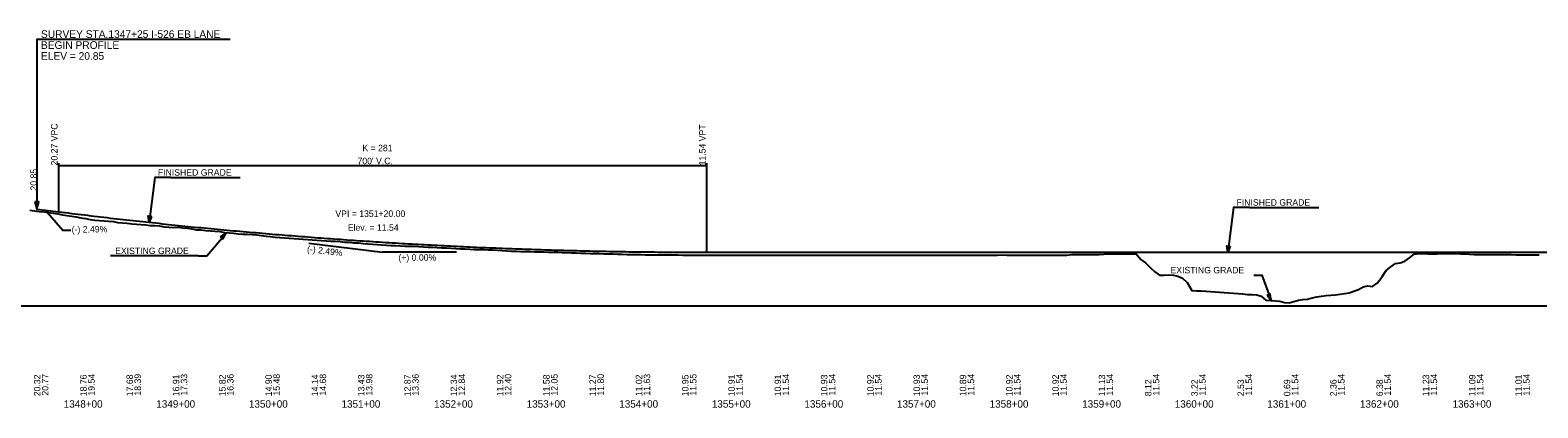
# Model space of a CAD drawing. Extents: x 2360994 to 2383826, y 330623 to 403123.
# Drawn here: x 2370065 to 2371693, y 356763 to 357170 of the extents above; entities that cross this region are included whole.
import ezdxf

# ---------------------------------------------------------------- set-up
doc = ezdxf.new("R2010")
doc.units = 0
for name, color, linetype in [('RD_DDB_GradeTX', 7, 'Continuous'), ('RD_DDB_Profile_EX', 7, 'Continuous'), ('RD_DDB_Profile_Lbl', 7, 'Continuous'), ('RD_DDB_Profile_PR', 7, 'Continuous'), ('RD_DDB_StaTX', 7, 'Continuous'), ('RD_DDB_StripGrade', 7, 'Continuous'), ('RD_DDB_VCLbl', 7, 'Continuous'), ('RD_GPK_Profile_Cell', 7, 'Continuous'), ('RD_TX_Profile', 7, 'Continuous')]:
    doc.layers.add(name, color=color, linetype=linetype)

msp = doc.modelspace()

# ---------------------------------------------------------------- linework, layer by layer
at = {"layer": 'RD_DDB_GradeTX'}
for p in [(2370366.2, 356940.5), (2370525.6, 356930.6)]:
    msp.add_line(p, (2370445.6, 356930.6), dxfattribs=at)
at = {"layer": 'RD_DDB_Profile_EX'}
for points in [[(2370064.8, 356975.9), (2370069.8, 356975.2), (2370074.8, 356974.6), (2370079.8, 356974), (2370084.8, 356973.5), (2370089.8, 356972.8), (2370094.8, 356972.1), (2370099.8, 356971), (2370104.8, 356970.1), (2370109.8, 356969.4), (2370114.8, 356968.6), (2370119.8, 356967.8), (2370124.8, 356966.8), (2370129.8, 356965.9), (2370134.8, 356965.3), (2370139.8, 356964.9), (2370144.8, 356964.4), (2370149.8, 356964), (2370154.8, 356963.6), (2370159.8, 356962.8), (2370164.8, 356962.2), (2370169.8, 356961.8), (2370174.8, 356961.4), (2370179.8, 356960.9), (2370184.8, 356960.4), (2370189.8, 356960), (2370194.8, 356959.5), (2370199.8, 356959.4), (2370204.8, 356959), (2370209.8, 356957.9), (2370214.8, 356957.5), (2370219.8, 356957.1), (2370224.8, 356957.5), (2370229.8, 356957), (2370234.8, 356956.5), (2370239.8, 356956), (2370244.8, 356954.7), (2370249.8, 356954.7), (2370254.8, 356954.2), (2370259.8, 356953.8), (2370264.8, 356953.4), (2370269.8, 356953), (2370274.8, 356952), (2370279.8, 356951.6), (2370284.8, 356951.1), (2370289.8, 356950.6), (2370294.8, 356950.2), (2370299.8, 356950), (2370304.8, 356949.6), (2370309.8, 356949.2), (2370314.8, 356948.7), (2370319.8, 356947.9), (2370324.8, 356947.5), (2370329.8, 356947), (2370334.8, 356946.6), (2370339.8, 356946.2), (2370344.8, 356945.7), (2370349.8, 356945.3), (2370354.8, 356944.9), (2370359.8, 356944.6), (2370364.8, 356944.2), (2370369.8, 356943.9), (2370374.8, 356943.6), (2370379.8, 356943.3), (2370384.8, 356943), (2370389.8, 356942.7), (2370394.8, 356942.4), (2370399.8, 356942), (2370404.8, 356941.6), (2370409.8, 356941.3), (2370414.8, 356940.9), (2370419.8, 356940.6), (2370424.8, 356940.1), (2370429.8, 356939.7), (2370434.8, 356939.4), (2370439.8, 356939.1), (2370444.8, 356938.7), (2370449.8, 356938.3), (2370454.8, 356938), (2370459.8, 356937.7), (2370464.8, 356937.4), (2370469.8, 356937.2), (2370474.8, 356937.3), (2370479.8, 356937), (2370484.8, 356936.8), (2370489.8, 356936.5), (2370494.8, 356936), (2370499.8, 356935.9), (2370504.8, 356935.7), (2370509.8, 356935.4), (2370514.8, 356935.2), (2370519.8, 356935), (2370524.8, 356934.6), (2370529.8, 356934.4), (2370534.8, 356934.2), (2370539.8, 356933.9), (2370544.8, 356933.7), (2370549.8, 356933.5), (2370554.8, 356933.4), (2370559.8, 356933.2), (2370564.8, 356933.1)], [(2370564.8, 356933.1), (2370569.8, 356932.8), (2370574.8, 356932.5), (2370579.8, 356932.2), (2370584.8, 356931.9), (2370589.8, 356931.6), (2370594.8, 356931.4), (2370599.8, 356931.4), (2370604.8, 356931.3), (2370609.8, 356931.2), (2370614.8, 356931.1), (2370619.8, 356930.9), (2370624.8, 356930.8), (2370629.8, 356930.6), (2370634.8, 356930.5), (2370639.8, 356930.3), (2370644.8, 356930.2), (2370649.8, 356930), (2370654.8, 356929.9), (2370659.8, 356929.7), (2370664.8, 356929.6), (2370669.8, 356929.4), (2370674.8, 356929.3), (2370679.8, 356929.1), (2370684.8, 356929), (2370689.8, 356928.9), (2370694.8, 356928.7), (2370699.8, 356928.5), (2370704.8, 356928.4), (2370709.8, 356928.2), (2370714.8, 356928), (2370719.8, 356928), (2370724.8, 356928), (2370729.8, 356927.9), (2370734.8, 356927.9), (2370739.8, 356927.9), (2370744.8, 356927.9), (2370749.8, 356927.8), (2370754.8, 356927.8), (2370759.8, 356927.7), (2370764.8, 356927.7), (2370769.8, 356927.6), (2370774.8, 356927.6), (2370779.8, 356927.6), (2370784.8, 356927.6), (2370789.8, 356927.5), (2370794.8, 356927.5), (2370799.8, 356927.4), (2370804.8, 356927.5), (2370809.8, 356927.5), (2370814.8, 356927.5), (2370819.8, 356927.5), (2370824.8, 356927.4), (2370829.8, 356927.4), (2370834.8, 356927.4), (2370839.8, 356927.4), (2370844.8, 356927.3), (2370849.8, 356927.3), (2370854.8, 356927.4), (2370859.8, 356927.4), (2370864.8, 356927.4), (2370869.8, 356927.3), (2370874.8, 356927.4), (2370879.8, 356927.4), (2370884.8, 356927.4), (2370889.8, 356927.4), (2370894.8, 356927.4), (2370899.8, 356927.4), (2370904.8, 356927.4), (2370909.8, 356927.4), (2370914.8, 356927.4), (2370919.8, 356927.5), (2370924.8, 356927.5), (2370929.8, 356927.5), (2370934.8, 356927.6), (2370939.8, 356927.6), (2370944.8, 356927.6), (2370949.8, 356927.6), (2370954.8, 356927.5), (2370959.8, 356927.5), (2370964.8, 356927.5), (2370969.8, 356927.5), (2370974.8, 356927.5), (2370979.8, 356927.4), (2370984.8, 356927.4), (2370989.8, 356927.4), (2370994.8, 356927.3), (2370999.8, 356927.4), (2371004.8, 356927.4), (2371009.8, 356927.4), (2371014.8, 356927.4), (2371019.8, 356927.5), (2371024.8, 356927.5), (2371029.8, 356927.6), (2371034.8, 356927.6), (2371039.8, 356927.6), (2371044.8, 356927.5), (2371049.8, 356927.5), (2371054.8, 356927.5), (2371059.8, 356927.5), (2371064.8, 356927.5)], [(2371064.8, 356927.5), (2371069.8, 356927.4), (2371074.8, 356927.4), (2371079.8, 356927.3), (2371084.8, 356927.3), (2371089.8, 356927.3), (2371094.8, 356927.4), (2371099.8, 356927.4), (2371104.8, 356927.4), (2371109.8, 356927.4), (2371114.8, 356927.8), (2371119.8, 356927.5), (2371124.8, 356927.5), (2371129.8, 356927.5), (2371134.8, 356927.5), (2371139.8, 356927.5), (2371144.8, 356927.6), (2371149.8, 356927.6), (2371154.8, 356927.6), (2371159.8, 356927.6), (2371164.8, 356927.4), (2371169.8, 356927.4), (2371174.8, 356927.5), (2371179.8, 356927.5), (2371184.8, 356927.5), (2371189.8, 356928), (2371194.8, 356928.3), (2371199.8, 356928.3), (2371204.8, 356928.3), (2371209.8, 356928.3), (2371214.8, 356928.3), (2371219.8, 356928.2), (2371224.8, 356928.5), (2371229.8, 356928.9), (2371234.8, 356928.9), (2371239.8, 356928.9), (2371244.8, 356928.9), (2371249.8, 356928.9), (2371254.8, 356928.9), (2371259.8, 356928.9), (2371264.8, 356922.9), (2371269.8, 356919.3), (2371274.8, 356914.2), (2371279.8, 356909.5), (2371284.8, 356905.9), (2371289.8, 356906), (2371294.8, 356906.1), (2371299.8, 356905.9), (2371304.8, 356904.8), (2371309.8, 356902.8), (2371314.8, 356897.9), (2371319.8, 356889.2), (2371324.8, 356889), (2371329.8, 356888.9), (2371334.8, 356888.5), (2371339.8, 356888.2), (2371344.8, 356887.8), (2371349.8, 356887.4), (2371354.8, 356887.1), (2371359.8, 356886.7), (2371364.8, 356886.3), (2371369.8, 356886), (2371374.8, 356885.6), (2371379.8, 356885.2), (2371384.8, 356884.9), (2371389.8, 356884.5), (2371394.8, 356883.2), (2371399.8, 356878.8), (2371404.8, 356878.6), (2371409.8, 356878.3), (2371414.8, 356877.8), (2371419.8, 356876.3), (2371424.8, 356876.1), (2371429.8, 356877.6), (2371434.8, 356878.9), (2371439.8, 356879.6), (2371444.8, 356880.1), (2371449.8, 356881.3), (2371454.8, 356882.5), (2371459.8, 356883.4), (2371464.8, 356884), (2371469.8, 356884.3), (2371474.8, 356884.6), (2371479.8, 356885.3), (2371484.8, 356886.1), (2371489.8, 356887), (2371494.8, 356888.7), (2371499.8, 356890.4), (2371504.8, 356893.3), (2371509.8, 356894.4), (2371514.8, 356893.5), (2371519.8, 356897.4), (2371524.8, 356903.7), (2371529.8, 356910.9), (2371534.8, 356914.7), (2371539.8, 356918.4), (2371544.8, 356919.3), (2371549.8, 356920.8), (2371554.8, 356924.6), (2371559.8, 356928.5), (2371564.8, 356929.1)], [(2371564.8, 356929.1), (2371569.8, 356929.1), (2371574.8, 356929), (2371579.8, 356929), (2371584.8, 356929), (2371589.8, 356929.1), (2371594.8, 356929.2), (2371599.8, 356929.2), (2371604.8, 356929.2), (2371609.8, 356928.9), (2371614.8, 356928.7), (2371619.8, 356928.4), (2371624.8, 356928.3), (2371629.8, 356928.3), (2371634.8, 356928.2), (2371639.8, 356928.1), (2371644.8, 356928.1), (2371649.8, 356928.1), (2371654.8, 356928), (2371659.8, 356928), (2371664.8, 356928), (2371669.8, 356927.9), (2371674.8, 356927.9), (2371679.8, 356927.9), (2371684.8, 356927.9), (2371689.8, 356927.9), (2371694.8, 356927.9)]]:
    msp.add_lwpolyline(points, dxfattribs=at)
at = {"layer": 'RD_DDB_Profile_PR'}
for p, q in [((2370072.3, 356977.1), (2370095.6, 356974.2)), ((2370795.6, 356930.6), (2370825.6, 356930.6)), ((2370825.6, 356930.6), (2372225.6, 356930.6))]:
    msp.add_line(p, q, dxfattribs=at)
msp.add_spline([(2370095.6, 356974.2), (2370109.6, 356972.5), (2370123.6, 356970.8), (2370137.6, 356969.2), (2370151.6, 356967.5), (2370165.6, 356965.9), (2370179.6, 356964.4), (2370193.6, 356962.9), (2370207.6, 356961.4), (2370221.6, 356959.9), (2370235.6, 356958.5), (2370249.6, 356957.1), (2370263.6, 356955.8), (2370277.6, 356954.5), (2370291.6, 356953.2), (2370305.6, 356952), (2370319.6, 356950.8), (2370333.6, 356949.6), (2370347.6, 356948.5), (2370361.6, 356947.4), (2370375.6, 356946.3), (2370389.6, 356945.3), (2370403.6, 356944.3), (2370417.6, 356943.3), (2370431.6, 356942.4), (2370445.6, 356941.5), (2370459.6, 356940.6), (2370473.6, 356939.8), (2370487.6, 356939), (2370501.6, 356938.3), (2370515.6, 356937.6), (2370529.6, 356936.9), (2370543.6, 356936.2), (2370557.6, 356935.6), (2370571.6, 356935.1), (2370585.6, 356934.5), (2370599.6, 356934), (2370613.6, 356933.5), (2370627.6, 356933.1), (2370641.6, 356932.7), (2370655.6, 356932.3), (2370669.6, 356932), (2370683.6, 356931.7), (2370697.6, 356931.4), (2370711.6, 356931.2), (2370725.6, 356931), (2370739.6, 356930.9), (2370753.6, 356930.7), (2370767.6, 356930.7), (2370781.6, 356930.6), (2370795.6, 356930.6)], degree=3, dxfattribs=at)
at = {"layer": 'RD_DDB_VCLbl'}
for p, q in [((2370095.6, 357026.7), (2370095.6, 356974.2)), ((2370095.6, 357024.2), (2370795.6, 357024.2)), ((2370795.6, 357026.7), (2370795.6, 356930.6))]:
    msp.add_line(p, q, dxfattribs=at)
at = {"layer": 'RD_GPK_Profile_Cell'}
msp.add_line((2368825.6, 356872.9), (2383825.6, 356872.9), dxfattribs=at)
at = {"layer": 'RD_TX_Profile'}
for p, q in [((2370216.8, 357011.1), (2370291.7, 357011.1)), ((2371381.9, 356978.8), (2371456.8, 356978.8)), ((2370246.9, 356926.6), (2370151.8, 356926.6))]:
    msp.add_line(p, q, dxfattribs=at)
for points in [[(2370281.1, 357159.9), (2370072.1, 357159.9), (2370072.3, 356977.1)], [(2370216.8, 357011.1), (2370199.8, 357011.1), (2370193.5, 356962.9)], [(2370108.9, 356954), (2370100.2, 356954), (2370081.3, 356976)], [(2371381.9, 356978.8), (2371364.9, 356978.8), (2371358.6, 356930.6)], [(2370246.9, 356926.6), (2370255.7, 356926.6), (2370276.5, 356950.9)], [(2371386.8, 356905.8), (2371395.5, 356905.8), (2371405.3, 356878.6)]]:
    msp.add_lwpolyline(points, dxfattribs=at)
for points in [[(2370070.2, 356985.1), (2370072.3, 356977.1), (2370074.4, 356985.1)], [(2370196.2, 356969.3), (2370193.5, 356962.9), (2370192.6, 356969.8)], [(2370273.3, 356944.7), (2370276.5, 356950.9), (2370270.6, 356947.1)], [(2371361.3, 356937.1), (2371358.6, 356930.6), (2371357.7, 356937.5)], [(2371401.2, 356884.2), (2371405.3, 356878.6), (2371404.5, 356885.5)]]:
    msp.add_lwpolyline(points, close=True, dxfattribs=at)

# ---------------------------------------------------------------- texts
at = {"layer": 'RD_DDB_GradeTX'}
for rotation, p in [(0.4794, (2370109.9, 356951.7)), (352.8909, (2370363.8, 356931))]:
    msp.add_text('(-) 2.49%', height=7, rotation=rotation, dxfattribs=at).set_placement(p)
msp.add_text('(+) 0.00%', height=7, dxfattribs=at).set_placement((2370462.8, 356921.4))
at = {"layer": 'RD_DDB_Profile_Lbl'}
msp.add_text('20.85', height=7, rotation=90, dxfattribs=at).set_placement((2370072.3, 356997.1))
for s, p in [('VPI = 1351+20.00', (2370394.7, 356968.7)), ('Elev. = 11.54', (2370408.1, 356953.7))]:
    msp.add_text(s, height=7, dxfattribs=at).set_placement(p)
at = {"layer": 'RD_DDB_StaTX'}
for s, p in [('1348+00', (2370101.3, 356763)), ('1349+00', (2370201.3, 356763)), ('1350+00', (2370301.3, 356763)), ('1351+00', (2370401.3, 356763)), ('1352+00', (2370501.3, 356763)), ('1353+00', (2370601.3, 356763)), ('1354+00', (2370701.3, 356763)), ('1355+00', (2370801.3, 356763)), ('1356+00', (2370901.3, 356763)), ('1357+00', (2371001.3, 356763)), ('1358+00', (2371101.3, 356763)), ('1359+00', (2371201.3, 356763)), ('1360+00', (2371301.3, 356763)), ('1361+00', (2371401.3, 356763)), ('1362+00', (2371501.3, 356763)), ('1363+00', (2371601.3, 356763))]:
    msp.add_text(s, height=8, dxfattribs=at).set_placement(p)
at = {"layer": 'RD_DDB_StripGrade'}
for s, p in [('20.27 VPC', (2370094.6, 357024.2)), ('11.54 VPT', (2370794.6, 357024.2)), ('20.32', (2370076.1, 356775.3)), ('20.77', (2370084.7, 356776)), ('18.76', (2370126.1, 356775.3)), ('19.54', (2370134.7, 356776)), ('17.68', (2370176.1, 356775.3)), ('18.39', (2370184.7, 356776)), ('16.91', (2370226.1, 356775.3)), ('17.33', (2370234.7, 356776)), ('15.82', (2370276.1, 356775.3)), ('16.36', (2370284.7, 356776)), ('14.90', (2370326.1, 356775.3)), ('15.48', (2370334.7, 356776)), ('14.14', (2370376.1, 356775.3)), ('14.68', (2370384.7, 356776)), ('13.43', (2370426.1, 356775.3)), ('13.98', (2370434.7, 356776)), ('12.87', (2370476.1, 356775.3)), ('13.36', (2370484.7, 356776)), ('12.34', (2370526.1, 356775.3)), ('12.84', (2370534.7, 356776)), ('11.92', (2370576.1, 356775.3)), ('12.40', (2370584.7, 356776)), ('11.58', (2370626.1, 356775.3)), ('12.05', (2370634.7, 356776)), ('11.27', (2370676.1, 356775.3)), ('11.80', (2370684.7, 356776)), ('11.02', (2370726.1, 356775.3)), ('11.63', (2370734.7, 356776)), ('10.95', (2370776.1, 356775.3)), ('11.55', (2370784.7, 356776)), ('10.91', (2370826.1, 356775.3)), ('11.54', (2370834.7, 356776)), ('10.91', (2370876.1, 356775.3)), ('11.54', (2370884.7, 356776)), ('10.93', (2370926.1, 356775.3)), ('11.54', (2370934.7, 356776)), ('10.92', (2370976.1, 356775.3)), ('11.54', (2370984.7, 356776)), ('10.93', (2371026.1, 356775.3)), ('11.54', (2371034.7, 356776)), ('10.89', (2371076.1, 356775.3)), ('11.54', (2371084.7, 356776)), ('10.92', (2371126.1, 356775.3)), ('11.54', (2371134.7, 356776)), ('10.92', (2371176.1, 356775.3)), ('11.54', (2371184.7, 356776)), ('11.13', (2371226.1, 356775.3)), ('11.54', (2371234.7, 356776)), ('8.12', (2371276.1, 356775.3)), ('11.54', (2371284.7, 356776)), ('3.22', (2371326.1, 356775.3)), ('11.54', (2371334.7, 356776)), ('2.53', (2371376.1, 356775.3)), ('11.54', (2371384.7, 356776)), ('0.69', (2371426.1, 356775.3)), ('11.54', (2371434.7, 356776)), ('2.36', (2371476.1, 356775.3)), ('11.54', (2371484.7, 356776)), ('6.38', (2371526.1, 356775.3)), ('11.54', (2371534.7, 356776)), ('11.23', (2371576.1, 356775.3)), ('11.54', (2371584.7, 356776)), ('11.09', (2371626.1, 356775.3)), ('11.54', (2371634.7, 356776)), ('11.01', (2371676.1, 356775.3)), ('11.54', (2371684.7, 356776))]:
    msp.add_text(s, height=7, rotation=90, dxfattribs=at).set_placement(p)
at = {"layer": 'RD_DDB_VCLbl'}
for s, p in [('K = 281', (2370423.9, 357039.5)), ("700' V.C.", (2370418.6, 357025.5))]:
    msp.add_text(s, height=7, dxfattribs=at).set_placement(p)
at = {"layer": 'RD_TX_Profile'}
for s, height, p in [('SURVEY STA.1347+25 I-526 EB LANE', 8.235, (2370076.7, 357161.7)), ('BEGIN PROFILE', 8.235, (2370076.7, 357149.9)), ('ELEV = 20.85', 8.235, (2370076.7, 357138.1)), ('FINISHED GRADE', 7, (2370203, 357013.1)), ('FINISHED GRADE', 7, (2371368, 356980.8)), ('EXISTING GRADE', 7, (2370156.8, 356928.6)), ('EXISTING GRADE', 7, (2371296.7, 356907.8))]:
    msp.add_text(s, height=height, dxfattribs=at).set_placement(p)

doc.saveas('drawing.dxf')
